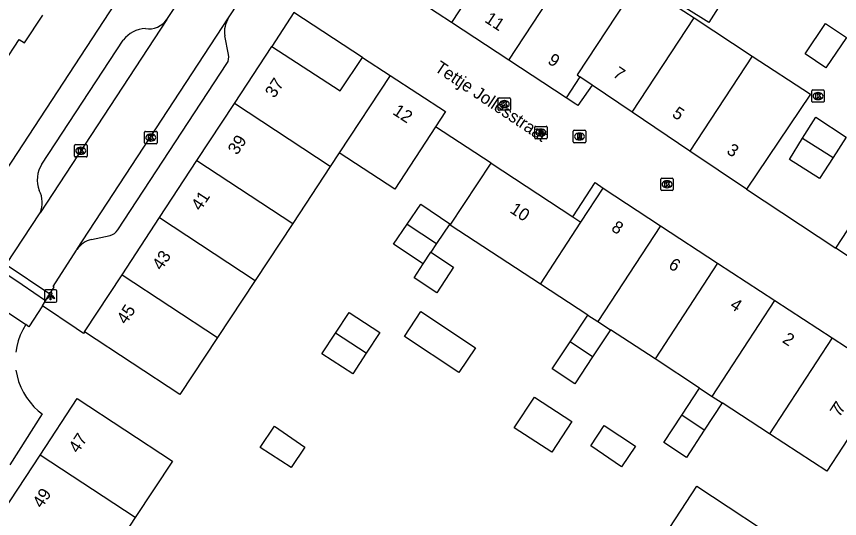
# Model space of a CAD drawing. Extents: x 159280 to 160375, y 384531 to 385872.
# Drawn here: x 159588.6 to 159655, y 385187.8 to 385228.3 of the extents above; entities that cross this region are included whole.
import ezdxf

# ---------------------------------------------------------------- set-up
doc = ezdxf.new("R2010")
doc.units = 0
for name, color, linetype in [('IMGEO_Kolk', 7, 'Continuous'), ('IMGEO_Lichtpunt', 7, 'Continuous'), ('IMGEO_Muur', 7, 'Continuous'), ('IMGEO_Openbare_ruimte_label', 7, 'Continuous'), ('IMGEO_Pand', 7, 'Continuous'), ('IMGEO_Pand_nummerreeks', 7, 'Continuous'), ('IMGEO_Pand_vergunning_verleend', 7, 'Continuous'), ('IMGEO_Rijbaan_lokaal_open', 7, 'Continuous'), ('IMGEO_Rioolput', 7, 'Continuous'), ('IMGEO_Voetpad_open', 7, 'Continuous')]:
    doc.layers.add(name, color=color, linetype=linetype)

msp = doc.modelspace()

# ---------------------------------------------------------------- linework, layer by layer
at = {"layer": 'IMGEO_Kolk'}
for p, q in [((159652.877, 385222.399), (159653.729, 385222.399)), ((159627.568, 385221.75), (159628.42, 385221.75)), ((159652.802, 385221.473), (159652.802, 385222.325)), ((159653.29, 385222.179), (159653.315, 385222.179)), ((159653.803, 385222.325), (159653.803, 385221.473)), ((159627.493, 385220.824), (159627.493, 385221.676)), ((159627.981, 385221.53), (159628.006, 385221.53)), ((159628.494, 385221.676), (159628.494, 385220.824)), ((159653.729, 385221.399), (159652.877, 385221.399)), ((159653.313, 385221.619), (159653.288, 385221.619)), ((159628.42, 385220.75), (159627.568, 385220.75)), ((159628.004, 385220.97), (159627.979, 385220.97)), ((159599.046, 385219.052), (159599.898, 385219.052)), ((159598.971, 385218.126), (159598.971, 385218.978)), ((159599.459, 385218.832), (159599.484, 385218.832)), ((159599.972, 385218.978), (159599.972, 385218.126)), ((159593.323, 385217.059), (159593.323, 385217.911)), ((159593.398, 385217.985), (159594.25, 385217.985)), ((159593.811, 385217.765), (159593.836, 385217.765)), ((159594.324, 385217.911), (159594.324, 385217.059)), ((159599.898, 385218.052), (159599.046, 385218.052)), ((159599.482, 385218.272), (159599.457, 385218.272)), ((159593.834, 385217.205), (159593.809, 385217.205)), ((159594.25, 385216.985), (159593.398, 385216.985)), ((159640.617, 385214.356), (159640.617, 385215.208)), ((159640.692, 385215.282), (159641.544, 385215.282)), ((159641.105, 385215.062), (159641.13, 385215.062)), ((159641.618, 385215.208), (159641.618, 385214.356)), ((159641.128, 385214.502), (159641.103, 385214.502)), ((159641.544, 385214.282), (159640.692, 385214.282))]:
    msp.add_line(p, q, dxfattribs=at)
for points in [[(159652.877, 385222.399), (159653.729, 385222.399)], [(159627.568, 385221.75), (159628.42, 385221.75)], [(159652.802, 385221.473), (159652.802, 385222.325)], [(159653.123, 385222.099), (159653.246, 385222.099), (159653.246, 385221.948), (159653.376, 385222.099), (159653.54, 385222.099), (159653.394, 385221.948), (159653.547, 385221.699), (159653.395, 385221.699), (159653.31, 385221.863), (159653.246, 385221.796), (159653.246, 385221.699), (159653.123, 385221.699), (159653.123, 385222.099)], [(159653.803, 385222.325), (159653.803, 385221.473)], [(159627.493, 385220.824), (159627.493, 385221.676)], [(159627.814, 385221.45), (159627.937, 385221.45), (159627.937, 385221.299), (159628.067, 385221.45), (159628.231, 385221.45), (159628.085, 385221.299), (159628.238, 385221.05), (159628.086, 385221.05), (159628.001, 385221.214), (159627.937, 385221.147), (159627.937, 385221.05), (159627.814, 385221.05), (159627.814, 385221.45)], [(159628.494, 385221.676), (159628.494, 385220.824)], [(159653.729, 385221.399), (159652.877, 385221.399)], [(159628.42, 385220.75), (159627.568, 385220.75)], [(159599.046, 385219.052), (159599.898, 385219.052)], [(159598.971, 385218.126), (159598.971, 385218.978)], [(159599.292, 385218.752), (159599.415, 385218.752), (159599.415, 385218.601), (159599.545, 385218.752), (159599.709, 385218.752), (159599.563, 385218.601), (159599.716, 385218.352), (159599.564, 385218.352), (159599.479, 385218.516), (159599.415, 385218.449), (159599.415, 385218.352), (159599.292, 385218.352), (159599.292, 385218.752)], [(159599.972, 385218.978), (159599.972, 385218.126)], [(159593.323, 385217.059), (159593.323, 385217.911)], [(159593.398, 385217.985), (159594.25, 385217.985)], [(159594.324, 385217.911), (159594.324, 385217.059)], [(159599.898, 385218.052), (159599.046, 385218.052)], [(159593.644, 385217.685), (159593.767, 385217.685), (159593.767, 385217.534), (159593.897, 385217.685), (159594.061, 385217.685), (159593.915, 385217.534), (159594.068, 385217.285), (159593.916, 385217.285), (159593.831, 385217.449), (159593.767, 385217.382), (159593.767, 385217.285), (159593.644, 385217.285), (159593.644, 385217.685)], [(159594.25, 385216.985), (159593.398, 385216.985)], [(159640.617, 385214.356), (159640.617, 385215.208)], [(159640.692, 385215.282), (159641.544, 385215.282)], [(159641.618, 385215.208), (159641.618, 385214.356)], [(159640.938, 385214.982), (159641.061, 385214.982), (159641.061, 385214.831), (159641.191, 385214.982), (159641.355, 385214.982), (159641.209, 385214.831), (159641.362, 385214.582), (159641.21, 385214.582), (159641.125, 385214.746), (159641.061, 385214.679), (159641.061, 385214.582), (159640.938, 385214.582), (159640.938, 385214.982)], [(159641.544, 385214.282), (159640.692, 385214.282)]]:
    msp.add_lwpolyline(points, dxfattribs=at)
for centre, start, end in [((159652.879, 385222.323), 91.55205, 178.44795), ((159652.879, 385222.323), 91.55205, 178.44795), ((159653.727, 385222.323), 1.55205, 88.44795), ((159653.727, 385222.323), 1.55205, 88.44795), ((159627.57, 385221.674), 91.55205, 178.44795), ((159627.57, 385221.674), 91.55205, 178.44795), ((159628.418, 385221.674), 1.55205, 88.44795), ((159628.418, 385221.674), 1.55205, 88.44795), ((159652.879, 385221.475), 181.55205, 268.44795), ((159652.879, 385221.475), 181.55205, 268.44795), ((159653.727, 385221.475), 271.55205, 358.44795), ((159653.727, 385221.475), 271.55205, 358.44795), ((159627.57, 385220.826), 181.55205, 268.44795), ((159627.57, 385220.826), 181.55205, 268.44795), ((159628.418, 385220.826), 271.55205, 358.44795), ((159628.418, 385220.826), 271.55205, 358.44795), ((159599.048, 385218.976), 91.55205, 178.44795), ((159599.048, 385218.976), 91.55205, 178.44795), ((159599.896, 385218.976), 1.55205, 88.44795), ((159599.896, 385218.976), 1.55205, 88.44795), ((159593.4, 385217.909), 91.55205, 178.44795), ((159593.4, 385217.909), 91.55205, 178.44795), ((159594.248, 385217.909), 1.55205, 88.44795), ((159594.248, 385217.909), 1.55205, 88.44795), ((159599.048, 385218.128), 181.55205, 268.44795), ((159599.048, 385218.128), 181.55205, 268.44795), ((159599.896, 385218.128), 271.55205, 358.44795), ((159599.896, 385218.128), 271.55205, 358.44795), ((159593.4, 385217.061), 181.55205, 268.44795), ((159593.4, 385217.061), 181.55205, 268.44795), ((159594.248, 385217.061), 271.55205, 358.44795), ((159594.248, 385217.061), 271.55205, 358.44795), ((159640.694, 385215.206), 91.55205, 178.44795), ((159640.694, 385215.206), 91.55205, 178.44795), ((159641.542, 385215.206), 1.55205, 88.44795), ((159641.542, 385215.206), 1.55205, 88.44795), ((159640.694, 385214.358), 181.55205, 268.44795), ((159640.694, 385214.358), 181.55205, 268.44795), ((159641.542, 385214.358), 271.55205, 358.44795), ((159641.542, 385214.358), 271.55205, 358.44795)]:
    msp.add_arc(centre, 0.0765, start, end, dxfattribs=at)
for centre, major_axis, ratio, start_param, end_param in [((159653.289, 385221.899), (-0.387, 0.002), 0.722429, 4.712389, 7.853982), ((159653.314, 385221.899), (-0.39, 0.002), 0.717154, 1.570796, 4.712389), ((159627.98, 385221.25), (-0.387, 0.002), 0.722429, 4.712389, 7.853982), ((159628.005, 385221.25), (-0.39, 0.002), 0.717154, 1.570796, 4.712389), ((159599.458, 385218.552), (-0.387, 0.002), 0.722429, 4.712389, 7.853982), ((159599.483, 385218.552), (-0.39, 0.002), 0.717154, 1.570796, 4.712389), ((159593.81, 385217.485), (-0.387, 0.002), 0.722429, 4.712389, 7.853982), ((159593.835, 385217.485), (-0.39, 0.002), 0.717154, 1.570796, 4.712389), ((159641.104, 385214.782), (-0.387, 0.002), 0.722429, 4.712389, 7.853982), ((159641.129, 385214.782), (-0.39, 0.002), 0.717154, 1.570796, 4.712389)]:
    msp.add_ellipse(centre, major_axis=major_axis, ratio=ratio, start_param=start_param, end_param=end_param, dxfattribs=at)
at = {"layer": 'IMGEO_Lichtpunt'}
for p, q in [((159590.883, 385206.174), (159590.883, 385205.367)), ((159590.883, 385206.174), (159590.883, 385205.367)), ((159591.785, 385206.269), (159590.977, 385206.269)), ((159591.785, 385206.269), (159590.977, 385206.269)), ((159591.879, 385205.367), (159591.879, 385206.174)), ((159591.879, 385205.367), (159591.879, 385206.174)), ((159590.977, 385205.273), (159591.785, 385205.273)), ((159590.977, 385205.273), (159591.785, 385205.273))]:
    msp.add_line(p, q, dxfattribs=at)
for points in [[(159591.257, 385205.838), (159591.296, 385205.81), (159591.108, 385205.548), (159591.07, 385205.575), (159591.257, 385205.838)], [(159591.359, 385205.79), (159591.406, 385205.79), (159591.406, 385205.468), (159591.359, 385205.468), (159591.359, 385205.79)], [(159591.469, 385205.81), (159591.507, 385205.837), (159591.694, 385205.575), (159591.655, 385205.547), (159591.469, 385205.81)]]:
    msp.add_lwpolyline(points, dxfattribs=at)
msp.add_circle((159591.382, 385205.972), 0.0994, dxfattribs=at)
for centre, start, end in [((159590.977, 385206.174), 90, 180), ((159590.977, 385206.174), 90, 180), ((159591.785, 385206.174), 0, 90), ((159591.785, 385206.174), 0, 90), ((159590.977, 385205.367), 180, 270), ((159590.977, 385205.367), 180, 270), ((159591.785, 385205.367), 270, 0), ((159591.785, 385205.367), 270, 360)]:
    msp.add_arc(centre, 0.0946, start, end, dxfattribs=at)
at = {"layer": 'IMGEO_Muur'}
msp.add_lwpolyline([(159626.926, 385216.485), (159622.443, 385219.423)], dxfattribs=at)
at = {"layer": 'IMGEO_Pand'}
for points in [[(159628.785, 385235.549), (159623.727, 385227.836)], [(159628.356, 385224.799), (159633.414, 385232.511)], [(159637.601, 385229.763), (159638.602, 385231.279), (159642.462, 385228.747), (159643.294, 385228.201)], [(159645.868, 385229.999), (159644.479, 385227.819), (159642.623, 385229), (159644.011, 385231.181)], [(159623.727, 385227.836), (159619.097, 385230.873)], [(159637.601, 385229.763), (159637.818, 385229.617), (159633.878, 385223.601), (159634.094, 385223.454)], [(159587.588, 385224.532), (159588.857, 385226.467), (159589.282, 385226.188), (159590.756, 385228.435)], [(159628.356, 385224.799), (159623.727, 385227.836)], [(159638.314, 385220.606), (159643.294, 385228.201)], [(159643.294, 385228.201), (159647.987, 385225.124)], [(159652.268, 385225.311), (159653.902, 385227.75), (159655.602, 385226.629), (159653.938, 385224.186), (159652.268, 385225.311)], [(159606.212, 385221.3), (159609.232, 385225.905)], [(159609.232, 385225.905), (159614.754, 385222.312), (159616.538, 385225.018)], [(159616.538, 385225.018), (159618.782, 385223.552)], [(159647.987, 385225.124), (159642.966, 385217.467)], [(159647.987, 385225.124), (159652.68, 385222.046), (159647.519, 385214.396)], [(159632.985, 385221.763), (159628.356, 385224.799)], [(159618.782, 385223.552), (159614.674, 385217.321)], [(159618.782, 385223.552), (159623.239, 385220.64), (159622.443, 385219.423)], [(159634.094, 385223.454), (159632.985, 385221.763)], [(159635.076, 385222.79), (159634.094, 385223.454)], [(159638.314, 385220.606), (159635.076, 385222.79)], [(159603.192, 385216.696), (159606.212, 385221.3)], [(159613.951, 385216.225), (159606.212, 385221.3)], [(159642.966, 385217.467), (159638.314, 385220.606)], [(159652.059, 385218.49), (159653.121, 385220.185), (159655.578, 385218.592), (159654.52, 385216.948)], [(159622.443, 385219.423), (159619.159, 385214.394), (159614.674, 385217.321)], [(159654.52, 385216.948), (159653.418, 385215.237), (159650.997, 385216.795), (159652.059, 385218.49)], [(159652.059, 385218.49), (159654.52, 385216.948)], [(159614.674, 385217.321), (159613.951, 385216.225)], [(159647.519, 385214.396), (159642.966, 385217.467)], [(159600.173, 385212.091), (159603.192, 385216.696)], [(159603.192, 385216.696), (159610.92, 385211.628)], [(159630.899, 385206.732), (159623.621, 385211.482), (159626.926, 385216.485)], [(159626.926, 385216.485), (159633.512, 385212.169)], [(159613.951, 385216.225), (159610.92, 385211.628)], [(159634.177, 385211.733), (159635.964, 385214.459)], [(159635.964, 385214.459), (159640.582, 385211.445)], [(159654.749, 385209.633), (159657.646, 385214.054), (159657.821, 385214.322), (159657.996, 385214.589), (159658.983, 385213.973)], [(159620.147, 385211.557), (159621.249, 385213.174), (159623.582, 385211.583), (159622.514, 385210.014)], [(159597.153, 385207.487), (159600.173, 385212.091)], [(159600.173, 385212.091), (159607.889, 385207.031)], [(159630.899, 385206.732), (159634.177, 385211.733)], [(159633.512, 385212.169), (159634.177, 385211.733)], [(159610.92, 385211.628), (159607.889, 385207.031)], [(159621.454, 385208.378), (159619.046, 385209.947), (159620.147, 385211.557)], [(159620.147, 385211.557), (159622.514, 385210.014)], [(159640.582, 385211.445), (159635.533, 385203.707)], [(159640.582, 385211.445), (159645.201, 385208.431)], [(159622.514, 385210.014), (159622.05, 385209.298)], [(159622.05, 385209.298), (159623.895, 385208.091), (159622.549, 385206.034), (159620.713, 385207.235), (159621.454, 385208.378)], [(159621.454, 385208.378), (159622.05, 385209.298)], [(159662.437, 385204.582), (159654.749, 385209.633)], [(159645.201, 385208.431), (159640.151, 385200.693)], [(159645.201, 385208.431), (159649.819, 385205.416)], [(159594.133, 385202.882), (159597.153, 385207.487)], [(159597.153, 385207.487), (159604.857, 385202.434)], [(159607.889, 385207.031), (159604.857, 385202.434)], [(159634.721, 385204.237), (159630.899, 385206.732)], [(159644.769, 385197.679), (159649.819, 385205.416)], [(159649.819, 385205.416), (159654.438, 385202.402)], [(159614.371, 385202.782), (159615.461, 385204.446), (159617.946, 385202.819), (159616.856, 385201.155)], [(159633.29, 385202.065), (159634.721, 385204.237)], [(159634.721, 385204.237), (159635.533, 385203.707)], [(159635.533, 385203.707), (159636.544, 385203.047)], [(159604.857, 385202.434), (159601.813, 385197.817), (159594.133, 385202.882)], [(159616.856, 385201.155), (159615.766, 385199.49), (159613.281, 385201.117), (159614.371, 385202.782)], [(159616.856, 385201.155), (159614.371, 385202.782)], [(159636.544, 385203.047), (159635.11, 385200.868)], [(159640.151, 385200.693), (159636.544, 385203.047)], [(159635.11, 385200.868), (159633.675, 385198.688), (159631.855, 385199.886), (159633.29, 385202.065)], [(159635.11, 385200.868), (159633.29, 385202.065)], [(159654.438, 385202.402), (159649.388, 385194.664)], [(159654.438, 385202.402), (159659.056, 385199.388)], [(159643.741, 385198.35), (159640.151, 385200.693)], [(159659.056, 385199.388), (159654.006, 385191.65), (159649.388, 385194.664)], [(159642.3, 385196.155), (159643.741, 385198.35)], [(159643.741, 385198.35), (159644.769, 385197.679)], [(159590.548, 385192.946), (159593.543, 385197.502), (159601.218, 385192.462), (159598.22, 385187.903)], [(159628.792, 385195.137), (159630.421, 385197.624), (159633.436, 385195.659), (159631.82, 385193.176), (159628.792, 385195.137)], [(159645.567, 385197.158), (159644.122, 385194.958)], [(159644.769, 385197.679), (159645.567, 385197.158)], [(159649.388, 385194.664), (159645.567, 385197.158)], [(159644.122, 385194.958), (159642.678, 385192.761), (159640.858, 385193.959), (159642.3, 385196.155)], [(159644.122, 385194.958), (159642.3, 385196.155)], [(159608.291, 385193.566), (159609.455, 385195.267), (159611.909, 385193.594), (159610.784, 385191.944), (159608.291, 385193.566)], [(159634.958, 385193.694), (159636.058, 385195.339), (159638.57, 385193.655), (159637.451, 385192.006), (159634.958, 385193.694)], [(159587.553, 385188.389), (159590.548, 385192.946)], [(159598.22, 385187.903), (159590.548, 385192.946)], [(159640.473, 385185.798), (159643.515, 385190.427), (159651.187, 385185.385), (159648.151, 385180.751)], [(159598.22, 385187.903), (159595.224, 385183.347)]]:
    msp.add_lwpolyline(points, dxfattribs=at)
at = {"layer": 'IMGEO_Pand_vergunning_verleend'}
msp.add_lwpolyline([(159619.934, 385202.509), (159621.267, 385204.517), (159625.658, 385201.601), (159624.324, 385199.593), (159619.934, 385202.509)], dxfattribs=at)
at = {"layer": 'IMGEO_Rijbaan_lokaal_open'}
for points in [[(159605.742, 385228.2), (159615.409, 385242.914), (159615.528, 385243.113)], [(159600.774, 385228.082), (159602.029, 385229.995)], [(159600.774, 385228.082), (159590.541, 385212.477)], [(159593.507, 385209.523), (159605.742, 385228.2)], [(159587.804, 385208.303), (159590.541, 385212.477)], [(159591.334, 385205.944), (159591.671, 385206.478), (159591.588, 385206.536), (159593.472, 385209.471), (159593.507, 385209.523)], [(159590.988, 385205.396), (159589.102, 385206.668), (159587.459, 385207.776)], [(159587.804, 385208.303), (159591.334, 385205.944)], [(159585.943, 385205.78), (159587.671, 385204.619), (159589.386, 385203.467)], [(159590.988, 385205.396), (159591.334, 385205.944)], [(159590.732, 385204.989), (159590.988, 385205.396)], [(159590.732, 385204.989), (159589.622, 385203.292), (159589.386, 385203.467)], [(159589.386, 385203.467), (159589.145, 385203.053), (159588.942, 385202.619), (159588.779, 385202.169), (159588.656, 385201.706), (159588.575, 385201.234)], [(159588.589, 385199.802), (159588.679, 385199.331), (159588.81, 385198.871), (159588.982, 385198.424), (159589.193, 385197.994), (159589.442, 385197.585), (159589.726, 385197.2), (159590.044, 385196.841), (159590.392, 385196.512), (159590.711, 385196.258), (159588.109, 385192.145)]]:
    msp.add_lwpolyline(points, dxfattribs=at)
at = {"layer": 'IMGEO_Rioolput'}
for p, q in [((159630.442, 385218.531), (159630.442, 385219.383)), ((159630.517, 385219.457), (159631.369, 385219.457)), ((159630.93, 385219.237), (159630.955, 385219.237)), ((159631.443, 385219.383), (159631.443, 385218.531)), ((159633.555, 385218.212), (159633.555, 385219.064)), ((159633.63, 385219.138), (159634.482, 385219.138)), ((159634.556, 385219.064), (159634.556, 385218.212)), ((159631.369, 385218.457), (159630.517, 385218.457)), ((159630.953, 385218.677), (159630.928, 385218.677)), ((159634.043, 385218.918), (159634.068, 385218.918)), ((159634.482, 385218.138), (159633.63, 385218.138)), ((159634.066, 385218.358), (159634.041, 385218.358))]:
    msp.add_line(p, q, dxfattribs=at)
for points in [[(159630.442, 385218.531), (159630.442, 385219.383)], [(159630.517, 385219.457), (159631.369, 385219.457)], [(159631.031, 385219.155), (159630.779, 385219.157), (159630.779, 385218.757)], [(159630.957, 385219.076), (159630.903, 385219.076), (159630.903, 385218.995)], [(159631.443, 385219.383), (159631.443, 385218.531)], [(159633.555, 385218.212), (159633.555, 385219.064)], [(159633.63, 385219.138), (159634.482, 385219.138)], [(159634.556, 385219.064), (159634.556, 385218.212)], [(159631.369, 385218.457), (159630.517, 385218.457)], [(159630.779, 385218.757), (159630.903, 385218.757), (159630.903, 385218.919), (159630.914, 385218.919)], [(159630.903, 385218.995), (159630.955, 385218.995)], [(159630.961, 385218.89), (159631.032, 385218.757), (159631.172, 385218.757), (159631.107, 385218.883)], [(159634.144, 385218.836), (159633.892, 385218.838), (159633.892, 385218.438)], [(159633.892, 385218.438), (159634.016, 385218.438), (159634.016, 385218.6), (159634.027, 385218.6)], [(159634.07, 385218.757), (159634.016, 385218.757), (159634.016, 385218.676)], [(159634.016, 385218.676), (159634.068, 385218.676)], [(159634.074, 385218.571), (159634.145, 385218.438), (159634.285, 385218.438), (159634.22, 385218.564)], [(159634.482, 385218.138), (159633.63, 385218.138)]]:
    msp.add_lwpolyline(points, dxfattribs=at)
for centre, radius, start, end in [((159630.519, 385219.381), 0.0765, 91.55205, 178.44795), ((159630.519, 385219.381), 0.0765, 91.55205, 178.44795), ((159630.963, 385218.98), 0.0964, 77.00612, 93.18647), ((159630.977, 385219.037), 0.0378, 276.66336, 79.67722), ((159631.03, 385219.045), 0.109, 350.36119, 89.41601), ((159631.367, 385219.381), 0.0765, 1.55205, 88.44795), ((159631.367, 385219.381), 0.0765, 1.55205, 88.44795), ((159633.632, 385219.062), 0.0765, 91.55205, 178.44795), ((159633.632, 385219.062), 0.0765, 91.55205, 178.44795), ((159634.48, 385219.062), 0.0765, 1.55205, 88.44795), ((159634.48, 385219.062), 0.0765, 1.55205, 88.44795), ((159630.519, 385218.533), 0.0765, 181.55205, 268.44795), ((159630.519, 385218.533), 0.0765, 181.55205, 268.44795), ((159630.913, 385218.866), 0.0533, 26.02933, 88.69889), ((159630.939, 385219.184), 0.19, 274.7715, 282.96867), ((159631.028, 385219.045), 0.112, 277.58423, 350.98172), ((159631.012, 385218.83), 0.108, 29.51342, 73.79051), ((159631.367, 385218.533), 0.0765, 271.55205, 358.44795), ((159631.367, 385218.533), 0.0765, 271.55205, 358.44795), ((159634.026, 385218.547), 0.0533, 26.02933, 88.69889), ((159634.052, 385218.865), 0.19, 274.7715, 282.96867), ((159634.076, 385218.661), 0.0964, 77.00612, 93.18647), ((159634.09, 385218.718), 0.0378, 276.66336, 79.67722), ((159634.143, 385218.726), 0.109, 350.36119, 89.41601), ((159634.141, 385218.726), 0.112, 277.58423, 350.98172), ((159634.125, 385218.511), 0.108, 29.51342, 73.79051), ((159633.632, 385218.214), 0.0765, 181.55205, 268.44795), ((159633.632, 385218.214), 0.0765, 181.55205, 268.44795), ((159634.48, 385218.214), 0.0765, 271.55205, 358.44795), ((159634.48, 385218.214), 0.0765, 271.55205, 358.44795)]:
    msp.add_arc(centre, radius, start, end, dxfattribs=at)
for centre, major_axis, ratio, start_param, end_param in [((159630.929, 385218.957), (-0.387, 0.002), 0.722429, 4.712389, 7.853982), ((159630.954, 385218.957), (-0.39, 0.002), 0.717154, 1.570796, 4.712389), ((159634.042, 385218.638), (-0.387, 0.002), 0.722429, 4.712389, 7.853982), ((159634.067, 385218.638), (-0.39, 0.002), 0.717154, 1.570796, 4.712389)]:
    msp.add_ellipse(centre, major_axis=major_axis, ratio=ratio, start_param=start_param, end_param=end_param, dxfattribs=at)
at = {"layer": 'IMGEO_Voetpad_open'}
for points in [[(159629.433, 385279.565), (159610.074, 385250), (159581.668, 385206.619)], [(159611.013, 385228.628), (159609.232, 385225.905)], [(159616.538, 385225.018), (159611.013, 385228.628)], [(159590.68, 385216.415), (159597.25, 385226.41)], [(159605.743, 385225.24), (159605.434, 385226.743)], [(159596.816, 385211.111), (159605.615, 385224.526)], [(159635.076, 385222.79), (159633.911, 385221.147), (159633.753, 385221.252), (159632.985, 385221.763)], [(159626.926, 385216.485), (159622.443, 385219.423)], [(159633.512, 385212.169), (159635.324, 385214.914), (159635.964, 385214.459)], [(159647.519, 385214.396), (159654.749, 385209.633)], [(159594.688, 385210.342), (159596.191, 385210.642)], [(159594.133, 385202.882), (159594.045, 385202.748), (159593.46, 385203.143), (159590.732, 385204.989)]]:
    msp.add_lwpolyline(points, dxfattribs=at)
for centre, radius, start, end in [((159599.298, 385229.124), 1.807, 261.81591, 324.7647), ((159607.598, 385227.047), 2.185, 148.13686, 187.99071), ((159599.079, 385225.068), 2.268, 90.94864, 143.73197), ((159604.798, 385225.041), 0.966, 327.78599, 11.88691), ((159592.687, 385215.145), 2.375, 147.68615, 201.33943), ((159588.563, 385213.308), 2.145, 337.2138, 26.9767), ((159595.802, 385211.811), 1.232, 288.39292, 325.3762), ((159595.204, 385208.337), 2.07, 104.42783, 145.05325)]:
    msp.add_arc(centre, radius, start, end, dxfattribs=at)

# ---------------------------------------------------------------- texts
at = {"layer": 'IMGEO_Openbare_ruimte_label'}
msp.add_text('Tettje Jollesstraat', height=1, rotation=326.37347, dxfattribs=at).set_placement((159622.293, 385223.971))
at = {"layer": 'IMGEO_Pand_nummerreeks'}
for s, rotation, p in [('11', 326.73407, (159626.341, 385227.915)), ('9', 326.7398, (159631.417, 385224.585)), ('7', 326.00068, (159636.676, 385223.52)), ('37', 56.74001, (159609.447, 385221.674)), ('12', 326.84293, (159618.917, 385220.477)), ('5', 325.98923, (159641.455, 385220.296)), ('39', 56.73428, (159606.438, 385217.086)), ('3', 326.00068, (159645.853, 385217.329)), ('41', 56.75147, (159603.481, 385212.577)), ('10', 326.76272, (159628.366, 385212.553)), ('8', 326.87158, (159636.548, 385211.092)), ('43', 56.73428, (159600.333, 385207.777)), ('6', 326.87731, (159641.16, 385208.082)), ('45', 56.74001, (159597.472, 385203.415)), ('4', 326.86012, (159646.119, 385204.847)), ('2', 326.87731, (159650.351, 385202.083)), ('7', 56.87179, (159655.199, 385196.222)), ('7', 56.87179, (159655.019, 385195.947)), ('47', 56.68271, (159593.595, 385193.03)), ('49', 56.68271, (159590.679, 385188.594))]:
    msp.add_text(s, height=1, rotation=rotation, dxfattribs=at).set_placement(p)

doc.saveas('drawing.dxf')
